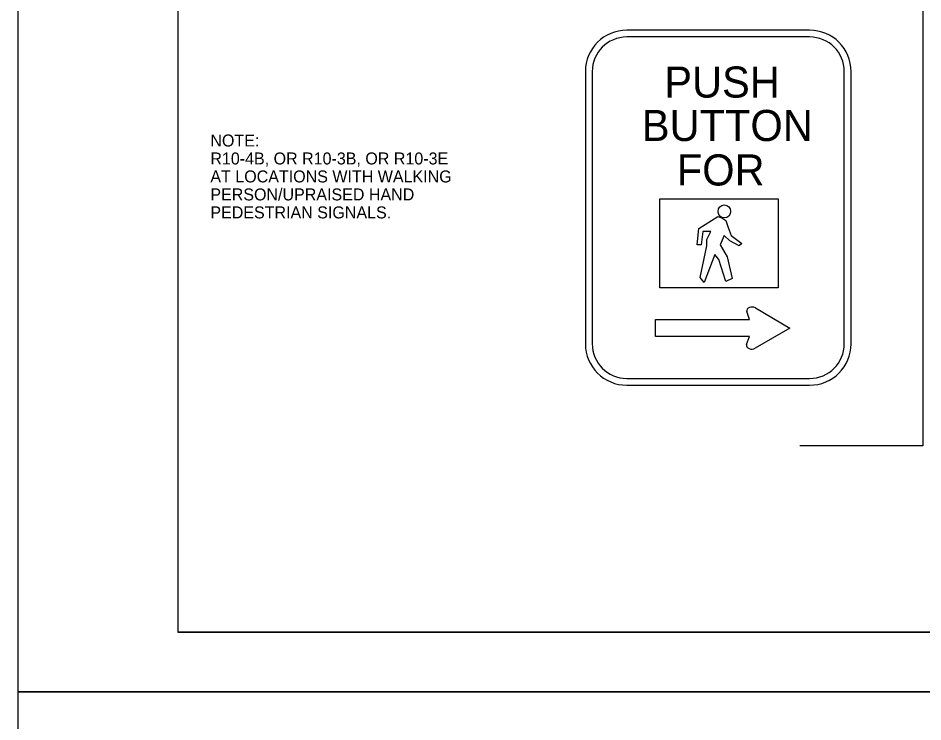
# Model space of a CAD drawing. Extents: x 36 to 940, y -1166 to 1210.
# Drawn here: x 35.9 to 262.3, y 608.7 to 784.9 of the extents above; entities that cross this region are included whole.
import ezdxf

# ---------------------------------------------------------------- set-up
doc = ezdxf.new("R2010")
doc.units = 0
for name, color, linetype in [('1', 7, 'Continuous'), ('2', 7, 'Continuous'), ('PLT-BNDY', 7, 'Continuous')]:
    doc.layers.add(name, color=color, linetype=linetype)

msp = doc.modelspace()

# ---------------------------------------------------------------- linework, layer by layer
at = {"layer": '1'}
for p, q in [((75.86, 1195.17), (75.86, 631.17)), ((861.86, 631.17), (75.86, 631.17)), ((75.86, 631.17), (661.86, 631.17))]:
    msp.add_line(p, q, dxfattribs=at)
at = {"layer": '2'}
for p, q in [((262.33, 910.3), (262.33, 677.76)), ((233.98, 781.84), (188.22, 781.84)), ((233.98, 780.14), (188.22, 780.14)), ((177.85, 771.47), (177.85, 703.33)), ((179.55, 771.47), (179.55, 703.33)), ((242.65, 703.33), (242.65, 771.47)), ((244.35, 703.33), (244.35, 771.47)), ((196.48, 717.34), (196.48, 739.59)), ((196.48, 739.59), (226.1, 739.59)), ((226.1, 739.59), (226.1, 717.34)), ((226.1, 717.34), (196.48, 717.34)), ((218.91, 709.41), (218.27, 711.41)), ((220.39, 712.31), (229.03, 707.28)), ((195.38, 705.15), (195.38, 709.42)), ((195.38, 709.42), (205.28, 709.41)), ((205.28, 709.41), (218.91, 709.41)), ((229.03, 707.28), (220.36, 702.24)), ((205.28, 705.16), (195.38, 705.15)), ((218.91, 705.16), (205.28, 705.16)), ((218.21, 703.14), (218.91, 705.16)), ((188.22, 694.66), (233.98, 694.66)), ((188.22, 692.96), (233.98, 692.96)), ((262.33, 677.76), (231.55, 677.76))]:
    msp.add_line(p, q, dxfattribs=at)
msp.add_lwpolyline([(216.98, 728.46), (216.35, 727.84), (213.98, 729.09), (212.6, 730.46), (211.6, 728.09), (213.35, 725.09), (214.6, 719.71), (212.98, 718.96), (211.23, 724.46), (210.23, 725.71), (207.6, 718.71), (206.6, 719.96), (208.23, 727.84), (208.23, 728.09), (208.23, 728.46), (208.23, 728.84), (208.23, 729.09), (208.23, 729.46), (209.23, 731.46), (207.23, 731.46), (206.85, 728.09), (205.85, 728.09), (206.23, 732.21), (210.98, 735.21), (211.98, 734.84), (212.98, 734.21), (213.6, 732.46), (214.35, 730.46)], close=True, dxfattribs=at)
for centre, radius, start, end in [((188.22, 771.47), 10.37, 90, 180), ((233.98, 771.47), 10.37, 0, 90), ((188.22, 771.47), 8.67, 90, 180), ((233.98, 771.47), 8.67, 0, 90), ((188.22, 703.33), 10.37, 180, 270), ((188.22, 703.33), 8.67, 180, 270), ((233.98, 703.33), 10.37, 270, 0), ((233.98, 703.33), 8.67, 270, 0)]:
    msp.add_arc(centre, radius, start, end, dxfattribs=at)
msp.add_ellipse((212.62, 736.46), major_axis=(0, -1.62), ratio=0.957031, dxfattribs=at)
for centre, start_param, end_param in [((219.55, 711.58), 4.011799, 6.466875), ((219.48, 702.95), 6.078068, 8.589712)]:
    msp.add_ellipse(centre, major_axis=(-1.3, 0), ratio=0.7337, start_param=start_param, end_param=end_param, dxfattribs=at)
at = {"layer": 'PLT-BNDY'}
for points in [[(35.86, 1210.17), (876.86, 1210.17), (876.86, 616.17), (35.86, 616.17)], [(35.86, 616.17), (876.86, 616.17), (876.86, 22.17), (35.86, 22.17)]]:
    msp.add_lwpolyline(points, close=True, dxfattribs=at)

# ---------------------------------------------------------------- texts
at = {"layer": '2'}
for s, height, p in [('PUSH', 7.784, (197.6, 764.96)), ('BUTTON', 7.784, (191.98, 754.09)), ('NOTE:', 3, (83.98, 752.72)), ('R10-4B, OR R10-3B, OR R10-3E', 3, (83.98, 748.22)), ('FOR', 7.784, (200.73, 742.96)), ('AT LOCATIONS WITH WALKING', 3, (83.98, 743.72)), ('PERSON/UPRAISED HAND', 3, (83.98, 739.22)), ('PEDESTRIAN SIGNALS.', 3, (83.98, 734.72))]:
    msp.add_text(s, height=height, dxfattribs=at).set_placement(p)

doc.saveas('drawing.dxf')
